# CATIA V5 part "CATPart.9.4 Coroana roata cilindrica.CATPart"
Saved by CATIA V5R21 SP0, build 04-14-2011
Part number: Coroana roata cilindrica
Bounding box of the stored display mesh (mm): x -79.081 to 79.022, y 0 to 179.067, z 0 to 40
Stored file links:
  C:\Users\MIRCEA\Desktop\MOM\Mogan\model\CATPart.9.4 Coroana roata cilindrica.CATPart
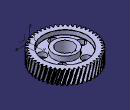
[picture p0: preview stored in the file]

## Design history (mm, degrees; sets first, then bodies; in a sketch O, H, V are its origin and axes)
Parameters
  `Date de intrare` = ""
  z1 = 15
  z2 = 49
  beta = 15 deg
  m_n = 3 mm
  aw = 100 mm
  xn1 = 0.208
  b1 = 40 mm
  b2 = 37 mm
  g = 3 mm
  `Date calculate si limita` = ""
  Ri2 = 69.3454 mm {= rf2-g}
  a = 99.3865 mm {= m_t * (z1 +z2 )/2}
  xn2 = 0.000851888 {= xsn - xn1}
  z1_min = 14
  aw_min = 98.1865 mm {= a - 0.4 * m_n}
  aw_max = 102.3865 mm {= a + m_n}
  x_min = -0.0714286 {= (-z1 + z1_min)/z1_min}
  s_an_min = 1.2 mm {= 0.4*m_n}
  epsilon_affa_min = 1.3
  `Unghiul de rotire` = ""
  ROT_1 = 0 deg
  `Alte date calculate` = ""
  u = 3.26667 {= z2 /z1}
  m_t = 3.1058 mm {= m_n / cos(beta )}
  alfat = 20.6469 deg {= atan(tan(alfa0_n )/cos(beta ))}
  alfawt = 21.5604 deg {= acos(a /aw * cos(alfat ) )}
  xsn = 0.208852 {= (tan(alfawt)-alfawt_r -tan(alfat) + alfat_r) * (z1 +z2 )/tan(alfa0_n)/2}
  aw_rec = 100 mm {= m_t * (z2 +z1 )*cos(alfat )/cos(alfawt )/2}
  rb1 = 21.7976 mm {= rd1 * cos(alfat )}
  rb2 = 71.2055 mm {= rd2 * cos(alfat )}
  rd1 = 23.2937 mm {= m_t *z1/2}
  rd2 = 76.0928 mm {= m_t *z2 /2}
  rw1 = 23.4375 mm {= aw/(u+1)}
  rw2 = 76.5625 mm {= aw-rw1}
  rf1 = 20.1677 mm {= m_n * (z1 /cos(beta )-2*(ha_n +c0_n-xn1 ))/2}
  rf2 = 72.3454 mm {= m_n * (z2 /cos(beta )-2*(ha_n +c0_n-xn2 ))/2}
  ra1 = 26.9046 mm {= (2*aw_rec  -m_n *(z2  /cos(beta )-2*(ha_n -xn2 )))/2}
  ra2 = 79.0823 mm {= (2*aw_rec  -m_n *(z1   /cos(beta )-2*(ha_n -xn1 )))/2}
  `Coordonate ale punctelor de pe evolventa 1` = ""
  Xe11 = 0.0083 mm {= rb1  *sqrt(1+(1*psi_r)  * (1*psi_r) ) * sin((1*phi) - atan((1*psi_r)))}
  Ye11 = 21.9168 mm {= rb1 *sqrt(1+(1*psi_r) * (1*psi_r) ) * cos((1*phi) - atan((1*psi_r )))}
  Xe12 = 0.0665 mm {= rb1  *sqrt(1+(2*psi_r )  * (2*psi_r)) * sin((2*phi) - atan((2*psi_r )))}
  Ye12 = 22.2704 mm {= rb1 *sqrt(1+(2*psi_r) * (2*psi_r) ) * cos((2*phi) - atan((2*psi_r )))}
  Xe13 = 0.2231 mm {= rb1  *sqrt(1+(3*psi_r)  * (3*psi_r) ) * sin((3*phi) - atan((3*psi_r)))}
  Ye13 = 22.8469 mm {= rb1 *sqrt(1+(3*psi_r) * (3*psi_r) ) * cos((3*phi) - atan((3*psi_r )))}
  Xe14 = 0.5247 mm {= rb1*sqrt(1+(4*psi_r)  * (4*psi_r) ) * sin((4*phi) - atan((4*psi_r)))}
  Ye14 = 23.6268 mm {= rb1 *sqrt(1+(4*psi_r) * (4*psi_r) ) * cos((4*phi) - atan((4*psi_r )))}
  Xe15 = 1.0147 mm {= rb1  *sqrt(1+(5*psi_r )  * (5*psi_r)) * sin((5*phi) - atan((5*psi_r )))}
  Ye15 = 24.5839 mm {= rb1 *sqrt(1+(5*psi_r) * (5*psi_r) ) * cos((5*phi) - atan((5*psi_r )))}
  Xe16 = 1.7321 mm {= rb1*sqrt(1+(6*psi_r )  * (6*psi_r)) * sin((6*phi) - atan((6*psi_r )))}
  Ye16 = 25.6848 mm {= rb1 *sqrt(1+(6*psi_r) * (6*psi_r) ) * cos((6*phi) - atan((6*psi_r )))}
  Xe17 = 2.7111 mm {= rb1  *sqrt(1+(7*psi_r )  * (7*psi_r)) * sin((7*phi) - atan((7*psi_r )))}
  Ye17 = 26.8904 mm {= rb1 *sqrt(1+(7*psi_r) * (7*psi_r) ) * cos((7*phi) - atan((7*psi_r )))}
  Xe18 = 3.9797 mm {= rb1  *sqrt(1+(8*psi_r )  * (8*psi_r)) * sin((8*phi) - atan((8*psi_r )))}
  Ye18 = 28.1561 mm {= rb1 *sqrt(1+(8*psi_r) * (8*psi_r) ) * cos((8*phi) - atan((8*psi_r )))}
  tetaC = 1.07882 {= (tan(alfawt ) - alfawt_r )*180/3.14159265}
  tetaC_g = 1.0788 deg {= tetaC *Angle}
  rho = 1.1647 mm {= rho_n *m_t}
  tau1 = 6 deg {= 360/z1 *Angle/4}
  tau2 = 1.8367 deg {= 360/z2 * Angle /4}
  Xe21 = 0.0272 mm {= Xe11 * u}
  Ye21 = 28.4052 mm {= aw_rec - Ye11 * u}
  Xe22 = 0.2171 mm {= Xe12 * u}
  Ye22 = 27.2499 mm {= aw_rec -Ye12 * u}
  Xe23 = 0.7287 mm {= Xe13 * u}
  Ye23 = 25.3669 mm {= aw_rec - Ye13 * u}
  X24 = 1.714 mm {= Xe14 * u}
  Ye24 = 22.8191 mm {= aw_rec -Ye14 * u}
  Xe25 = 3.3146 mm {= Xe15 * u}
  Ye25 = 19.6927 mm {= aw_rec -Ye15 * u}
  Xe26 = 5.6583 mm {= Xe16 * u}
  Ye26 = 16.0962 mm {= aw_rec - Ye16 * u}
  Xe27 = 8.8563 mm {= Xe17 *u}
  Ye27 = 12.1579 mm {= aw_rec -Ye17 * u}
  Xe28 = 13.0004 mm {= Xe18 * u}
  Ye28 = 8.0235 mm {= aw_rec -Ye18 * u}
  rot2 = 0 deg {= - ROT_1/u}
  pbt = 9.1306 mm {= PI * m_t * cos(alfat)}
  phi = 6 deg
  Angle = 1 deg
  alfat_r = 0.360356 {= alfat}
  alfawt_r = 0.376301 {= alfawt}
  psi_r = 0.10472 {= phi}
  `Parametri cremaliera` = ""
  alfa0_n = 20 deg
  ha_n = 1
  c0_n = 0.25
  rho_n = 0.375
AxisSystem1: origin (0, 0, 0), X (1, 0, 0), Y (0, 1, 0), Z (0, 0, 1)
Set1
  Point1: type OnPlane, Support xy-plane, H 0, V 21.7976 {= rb1}, Direction (1, 0, 0)
  Point2: type OnPlane, Support xy-plane, H 0.0083 {= Xe11}, V 21.9168 {= Ye11}, Direction (1, 0, 0)
  Point3: type OnPlane, Support xy-plane, H 0.0665 {= Xe12}, V 22.2704 {= Ye12}, Direction (1, 0, 0)
  Point4: type OnPlane, Support xy-plane, H 0.2231 {= Xe13}, V 22.8469 {= Ye13}, Direction (1, 0, 0)
  Point5: type OnPlane, Support xy-plane, H 0.5247 {= Xe14}, V 23.6268 {= Ye14}, Direction (1, 0, 0)
  Point6: type OnPlane, Support xy-plane, H 1.0147 {= Xe15}, V 24.5839 {= Ye15}, Direction (1, 0, 0)
  Point7: type OnPlane, Support xy-plane, H 1.7321 {= Xe16}, V 25.6848 {= Ye16}, Direction (1, 0, 0)
  Point8: type OnPlane, Support xy-plane, H 2.7111 {= Xe17}, V 26.8904 {= Ye17}, Direction (1, 0, 0)
  Point9: type OnPlane, Support xy-plane, H 3.9797 {= Xe18}, V 28.1561 {= Ye18}, Direction (1, 0, 0)
  Circle1: type CtrRad, Start 60, End 120, Center vertex [YZ plane of AxisSystem1 | ZX plane of AxisSystem1 | XY plane of AxisSystem1], Support xy-plane, Radius 20.1677 {= rf1}, FirstDirection (1, 0, 0)
  Circle2: type CtrRad, Start 60, End 120, Center vertex [YZ plane of AxisSystem1 | ZX plane of AxisSystem1 | XY plane of AxisSystem1], Support xy-plane, Radius 26.9046 {= ra1}, FirstDirection (1, 0, 0)
  Line1: type Angle, RefPoint vertex [YZ plane of AxisSystem1 | ZX plane of AxisSystem1 | XY plane of AxisSystem1], Curve Y axis, Support xy-plane, Start 0, End 30.2677 {= ra1 + ra1 /8}, Angle -7.0788 {= -tetaC_g - tau1}
  Line2: type Angle, RefPoint vertex of Line1, Curve Y axis, Support xy-plane, Start 0, End 22.1845 {= rf1 +rf1 /10}, Angle 4.9212 {= -tetaC_g + tau1}
  Point10: type OnPlane, Support xy-plane, H 0, V 21.5796 {= rb1 - rb1 /100}, Direction (1, 0, 0)
  Point11: type OnPlane, Support xy-plane, H 0, V 21.3616 {= rb1 - 1/50 * rb1}, Direction (1, 0, 0)
  Point12: type OnPlane, Support xy-plane, H 0, V 20.7077 {= rb1 - rb1 /20}, Direction (1, 0, 0)
  Point13: type OnPlane, Support xy-plane, H 0, V 19.6178 {= rb1 - rb1 /10}, Direction (1, 0, 0)
  Point14: type OnPlane, Support xy-plane, H 0, V 17.4381 {= rb1 -rb1 /5}, Direction (1, 0, 0)
  Point15: type OnPlane, Support xy-plane, H 0, V 14.5317 {= rb1 - rb1 /3}, Direction (1, 0, 0)
  Curve1: Elements (Point15; Point14; Point13; Point12; Point11; Point10; Point1; Point2; Point3; Point4; Point5; Point6; Point7; Point8; Point9)
  Trim1: Trimmed (Circle2; Curve1)
  Trim2: Trimmed (Line1; Trim1)
  Circle3: type CtrRad, Start 80, End 100, Center vertex [YZ plane of AxisSystem1 | ZX plane of AxisSystem1 | XY plane of AxisSystem1], Support xy-plane, Radius 17.1677 {= rf1 - g}, FirstDirection (1, 0, 0)
  Corner1: Element1 Circle1, Element2 Trim2, Radius 1.125
  Trim3: Trimmed (Circle1; Corner1)
  Trim4: Trimmed (Trim2; Trim3)
  Trim5: Trimmed (Trim4; Line2)
  Trim6: Trimmed (Trim5; Circle3)
  Point16: type OnPlane, Support xy-plane, H 0, V 100 {= aw_rec}, Direction (1, 0, 0)
  Circle4: type CtrRad, Start -80, End -100, Center Point16, Support xy-plane, Radius 72.3454 {= rf2}, FirstDirection (1, 0, 0)
  Circle5: type CtrRad, Start -80, End -100, Center Point16, Support xy-plane, Radius 79.0823 {= ra2}, FirstDirection (1, 0, 0)
  Point17: type OnPlane, Support xy-plane, H -0.0272 {= -Xe21}, V 28.4052 {= Ye21}, Direction (1, 0, 0)
  Point18: type OnPlane, Support xy-plane, H -0.2171 {= -Xe22}, V 27.2499 {= Ye22}, Direction (1, 0, 0)
  Point19: type OnPlane, Support xy-plane, H -0.7287 {= -Xe23}, V 25.3669 {= Ye23}, Direction (1, 0, 0)
  Point20: type OnPlane, Support xy-plane, H -1.714 {= -X24}, V 22.8191 {= Ye24}, Direction (1, 0, 0)
  Point21: type OnPlane, Support xy-plane, H -1.714 {= -X24}, V 22.8191 {= Ye24}, Direction (1, 0, 0)
  Point22: type OnPlane, Support xy-plane, H -3.3146 {= -Xe25}, V 19.6927 {= Ye25}, Direction (1, 0, 0)
  Point23: type OnPlane, Support xy-plane, H -5.6583 {= -Xe26}, V 16.0962 {= Ye26}, Direction (1, 0, 0)
  Point24: type OnPlane, Support xy-plane, H -8.8563 {= -Xe27}, V 12.1579 {= Ye27}, Direction (1, 0, 0)
  Point25: type OnPlane, Support xy-plane, H -13.0004 {= -Xe28}, V 8.0235 {= Ye28}, Direction (1, 0, 0)
  Point26: type OnPlane, Support xy-plane, H 0, V 28.7945 {= aw_rec - rb2}, Direction (1, 0, 0)
  Point27: type OnPlane, Support xy-plane, H 0, V 29.5066 {= aw_rec - rb2 +rb2 /100}, Direction (1, 0, 0)
  Point28: type OnPlane, Support xy-plane, H 0, V 30.2187 {= aw_rec - rb2 + rb2/50}, Direction (1, 0, 0)
  Point29: type OnPlane, Support xy-plane, RefPoint vertex [YZ plane of AxisSystem1 | ZX plane of AxisSystem1 | XY plane of AxisSystem1], H 0, V 32.3548 {= aw_rec - rb2 +rb2 /20}, Direction (1, 0, 0)
  Point30: type OnPlane, Support xy-plane, H 0, V 35.9151 {= aw_rec - rb2 +rb2 /10}, Direction (1, 0, 0)
  Circle6: type CtrRad, Start -80, End -100, Center Point16, Support xy-plane, Radius 69.3454 {= rf2 - g}, FirstDirection (1, 0, 0)
  Line3: type Angle, RefPoint Point16, Curve Y axis, Support xy-plane, Start 0, End 82.0823 {= ra2 + g}, Angle 177.0844 {= Angle *180-tau2 - tetaC_g}
  Line4: type Angle, RefPoint Point16, Curve Y axis, Support xy-plane, Start 0, End 82.0823 {= ra2 + g}, Angle 180.7579 {= Angle *180 + tau2 -tetaC_g}
  Point31: type OnPlane, Support xy-plane, H 0, V 43.0356 {= aw_rec - rb2 +rb2 /5}, Direction (1, 0, 0)
  Curve2: Elements (Point25; Point24; Point23; Point22; Point21; Point19; Point18; Point17; Point26; Point27; Point28; Point29; Point30; Point31)
  Corner2: Element1 Curve2, Element2 Circle4, Support xy-plane, Radius 1.1647 {= rho}
  Trim7: Trimmed (Line3; Circle5)
  Trim8: Trimmed (Trim7; Curve2)
  Trim9: Trimmed (Line4; Circle6)
  Trim10: Trimmed (Circle4; Corner2)
  Trim11: Trimmed (Trim8; Trim10)
  Trim12: Trimmed (Trim11; Trim9)
  Rotate1: ToTransfor Trim6, Axis Z axis, Angle 1.0788 {= tetaC_g}
  Line5: type PtDir, RefPoint Point16, Direction (0, 0, 1), Start 0, End 46.4066
  Rotate2: ToTransfor Trim12, Axis Line5, Angle 1.0788 {= tetaC_g}
  Rotate3: ToTransfor Rotate1, Axis Z axis, Angle 0 {= ROT_1}
  Rotate4: ToTransfor Rotate2, Axis Line5, Angle 0 {= rot2}
  Symmetry1: ToTransfor Rotate3, Reference {plane type 2Lines, Element1 edge of Rotate3, Element2 Z axis}
  Symmetry2: ToTransfor Rotate4, Reference {plane type 2Lines, Element1 edge of Rotate4, Element2 Line5}
  Translate1: ToTransfor Rotate4, Direction Line5, Length 37 {= b2}
  Translate2: ToTransfor Symmetry2, Direction Line5, Length 37 {= b2}
  Rotate5: ToTransfor Translate1, Axis Line5, Angle 7.4651 {= b2/rb2*tan(beta)*cos(alfat)}
  Rotate6: ToTransfor Translate2, Axis Line5, Angle 7.4651 {= b2/rb2*tan(beta)*cos(alfat)}
  Loft1: Sections (Rotate4; Rotate5)
  Loft2: Sections (Symmetry2; Rotate6)
  CircPattern1: of Loft1, instances 49 {= z2}, angular step 7.3469 {= 360.0*1 deg/CircPattern1.AngularNumber}, axis from Line5
  CircPattern2: of Loft2, instances 49 {= z2}, angular step 7.3469 {= 360.0*1 deg/CircPattern2.AngularNumber}, axis from Line5
  Add1: tool CircPattern2
  Translate3: ToTransfor Add1, Direction Line5, Length 1.5 {= (b1-b2)/2}
  Rotate7: ToTransfor Translate3, Axis Line5, Angle 0.3026 {= (b1-b2)/2/rb2*tan(beta)*cos(alfat)}
  Plane1: type Offset, RefPlane xy-plane, Offset 45
Body1 (main body)
  Sketch1 on yz-plane, origin (0, 0, 0), H (0, 1, 0), V (0, 0, 1)
    line L1 (77.5, 0) -> (77.5, 40)
    point P2 (77.5, 40)
    line L2 (67.5, 26) -> (40, 26)
    point P4 (40, 26)
    line L3 (40, 26) -> (40, 38.5)
    point P5 (40, 38.5)
    line L4 (40, 38.5) -> (30.655, 38.5)
    point P6 (30.655, 38.5)
    line L5 (30.655, 38.5) -> (30.655, 1.5)
    point P7 (30.655, 1.5)
    line L6 (30.655, 1.5) -> (40, 1.5)
    point P8 (40, 1.5)
    line L7 (40, 1.5) -> (40, 14)
    point P9 (40, 14)
    line L8 (40, 14) -> (67.5, 14)
    line L9 (67.5, 14) -> (67.5, 0)
    line L10 (67.5, 0) -> (77.5, 0)
    reference projected line E1 (100, 0) -> (100, 46.4066) from Line5
    reference projected line E2 (100, 0) -> (100, 46.4066) from Line5
    line L11 (67.5, 26) -> (67.5, 40)
    point P12 (67.5, 40)
    line L12 (77.5, 40) -> (67.5, 40)
    reference projected line E3 (96.9181, 38.5) -> (99.2417, 38.5) from edge [face of Rotate7 | face of Rotate7]
    reference projected line E4 (100, 0) -> (100, 46.4066) from Line5
    reference projected line E5 (100, 0) -> (100, 46.4066) from Line5
    length L1 = 40
    distance P4 P9 = 12
    distance P5 E1 = 60
    distance E2 P6 = 69.345
    distance P6 P7 = 37
    distance P9 P8 = 12.5
    length L11 = 14
    distance L12 E3 = 1.5
    distance E4 P2 = 22.5
    distance E5 P12 = 32.5
    vertical: L1 V, L3 V, L5 V, L7 V, L9 V, L11 V
    horizontal: L2 H, L4 H, L6 H, L8 H, L10 H, L12 H
    coincidence: P8 L3
  Shaft1: profile Sketch1, axis Line5, angle 360
  Add2: tool Rotate7
  Sketch2 on face of Shaft1 from Sketch1.L2, origin (37.5499, 74.8298, 26), H (1, 0, 0), V (0, 1, 0)
    point P1 (0.977, -0.3697)
    construction circle A1 centre (-37.5226, 24.8406) radius 47.3878
  Hole1: placed by Sketch2, at (38.5269, 74.4602, 26) direction (0, 0, -1), diameter 23, depth 30
  CircPattern3: of Hole1, instances 5, angular step 72 {= 360.0*1 deg/CircPattern3.AngularNumber}, axis from face of Shaft1 from Sketch1.L2
  Sketch3 on Plane1, origin (0, 0, 45), H (1, 0, 0), V (0, 1, 0)
    point P1 (0, 122.5)
    line L1 (7, 124.4) -> (7, 120.6)
    line L2 (7, 120.6) -> (-7, 120.6)
    line L3 (-7, 120.6) -> (-7, 124.4)
    line L4 (-7, 124.4) -> (7, 124.4)
    point P2 (7, 124.4)
    point P3 (7, 120.6)
    point P5 (-7, 124.4)
    distance P1 H = 122.5
    distance P5 P2 = 14
    distance P3 P2 = 3.8
    coincidence: P1 V
    vertical: L1 V, L3 V
    horizontal: L2 H, L4 H
    equidistance: L1 L3 P1, L2 L4 P1
  Pocket1: profile Sketch3, direction (0, 0, -1), length 60
  Chamfer1: length 0.5, angle 45, on edge [face of Shaft1 | face of Shaft1 from Sketch1.L3]; face of Shaft1 from Sketch1.L7; edge [face of Shaft1 from Sketch1.L3 | face of Shaft1 from Sketch1.L2]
